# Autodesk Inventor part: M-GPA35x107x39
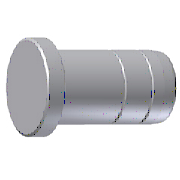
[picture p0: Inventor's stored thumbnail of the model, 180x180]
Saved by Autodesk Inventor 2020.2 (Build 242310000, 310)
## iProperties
Manager: www.cadconsulting.pl
Company: Fabian Stasiak CAD Consulting
Created: 2014-02
Part Number: M-GPA35x107x39
Material: SUJ 2
Description: GUIDE PIN
Document SubType Name: Modeling
Designer: F.Stasiak
Standard Revision: 1
Manufacturer: FUTABA
Language: pl-PL
Size Designation: 35x107x39
Categories: <MemberInstance><Categories><Category DisplayName="Forma wtryskowa" InternalName="349578f2-f4d4-4954-8c09-8e99297a61c0" Mnemonic="MOLD"><Category DisplayName="K
Mass: 12.6115 g
Surface Area: 36.5267 cm^2
Volume: 12.6115 cm^3
Density: 7.85 g/cm^3
Appearance: Domyślna
Catalog Web Link: www.expertbooks.pl
IsCustomPart: 0
Author: F.Stasiak
Subject: Zbiór ćwiczeń. Autodesk Inventor 2020. Kurs Professional
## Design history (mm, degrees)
sketch "Sketch1"
  geometry: L1 (0, -114.465)-(0, 26.077) reference; L2 (0, 8)-(20, 8); L3 (20, 8)-(20, 0); L4 (20, 0)-(17, 0); L5 (17, 0)-(17, -1.5); L6 (17, -1.5)-(17.5, -1.5); L7 (17.5, -1.5)-(17.5, -31); L8 (17.5, -31)-(17.5, -31); L9 (17.5, -31)-(17.5, -92); L10 (17.5, -92)-(17.047, -97.174); L11 (15.055, -99)-(0, -99); L12 (0, 8)-(0, -99); A1 r 2 centre (15.055, -97) between (15.055, -99) and (17.047, -97.174); 2 further points
  constraints: 30 end point, 5 perpendicular, 4 parallel, 4 point on line, 2 point on circle, 2 tangent, 1 centre point, 1 collinear, 1 horizontal alignment
  dimensions: "d0" = 40 diameter of L3 L1 (= D); "d2" = 1.5 distance of L4.end L5.end; "d3" = 8 distance between parallel lines of L4 L2 (= H_); "d5" = 0.5 distance between parallel lines of L7 L5; "d6" = 39 distance between parallel lines of L2 L8 (= N_); "d7" = 35 diameter of L7 L1 (= d1); "d8" = 107 distance between parallel lines of L2 L11 (= L); "d9" = 35 diameter of L9 L1 (= d_); "d10" = 7 vertical distance of L9.end point (16.888, -99) (= E_); "d11" = 5 deg angle of L9 L10; "d12" = 2 radius of A1
revolve "Revolution1" sketch "Sketch1" stored, may be unused: angle "d18" = 90 deg
sketch "Sketch2"
  geometry: L1 (17.5, -1.5)-(17.5, -92) reference; C1 r 0.5 at (17.5, -20.667)
  constraints: 1 centre point, 1 point on line
  dimensions: "d31" = 1 diameter of C1; "d68" = 71.33333 distance of L1.end C1.centre (derived)
coil "Coil1" sketch "Sketch2" pitch "d37" = 22.66667 (= P); turns "d39" = 3; dims "d38" = 53.5 (derived), "d40" = 0, angle "d41" = 90 deg, angle "d42" = 90 deg, "d43" = 0, "d44" = 0
sketch "Sketch3"
  geometry: L1 (0.5, 0)-(-0.5, 0); A1 r 0.5 centre (0, 0) between (-0.5, 0) and (0.5, 0) reference; A2 r 0.5 centre (0, 0) between (-0.5, 0) and (0.5, 0)
  constraints: 2 end point, 2 point on circle, 1 centre point, 1 coincident, 1 horizontal, 1 midpoint
  dimensions: "d71" = 0.5 radius of A2
revolve "Revolution2" sketch "Sketch3" stored, may be unused: angle "d54" = 90 deg
sketch "Sketch4"
  geometry: L1 (-0.5, 0)-(0.5, 0); A1 r 0.5 centre (0, 0) between (-0.5, 0) and (0.5, 0) reference; A2 r 0.5 centre (0, 0) between (-0.5, 0) and (0.5, 0)
  constraints: 2 end point, 2 point on circle, 1 centre point, 1 coincident, 1 horizontal, 1 midpoint
  dimensions: "d72" = 0.5 radius of A2
revolve "Revolution3" sketch "Sketch4" stored, may be unused: angle "d55" = 90 deg
sketch "Sketch5"
  geometry: L1 (17.5, -1.5)-(17.5, -92) reference; L2 (0, -106.8)-(0, 17.8) reference; C1 r 0.5 at (17.5, -29.583); C2 r 0.5 at (17.5, -65.25); 1 further point
  constraints: 2 centre point, 2 point on line, 1 equal radius
  dimensions: "d59" = 1 diameter of C1; "d61" = 35.66667 distance of C2.centre C1.centre (derived); "d69" = 26.75 distance of L1.end C2.centre (derived)
revolve "Revolution4" sketch "Sketch5" stored, may be unused: angle "d70" = 90 deg
fillet "Fillet1" dims "d63" = 0.3
chamfer "Chamfer1" distance "d64" = 0.5; stored, may be unused: second distance "d65" = 2, angle "d66" = 45 deg
body "Solid1"
other parameters: "d_" = 35 [user parameter; used in 1 equation term], "L" = 107 [user parameter; used in 1 equation term], "d1" = 35 [user parameter; used in 1 equation term], "H_" = 8 [user parameter; used in 1 equation term], "D" = 40 [user parameter; used in 1 equation term], "N_" = 39 [user parameter; used in 1 equation term], "S_" = 45.33333 [user parameter], "P" = 22.66667 [user parameter; used in 1 equation term], "d56" = 0, "d58" = 0, "E_" = 7 [user parameter; used in 1 equation term], "d67" = 0
